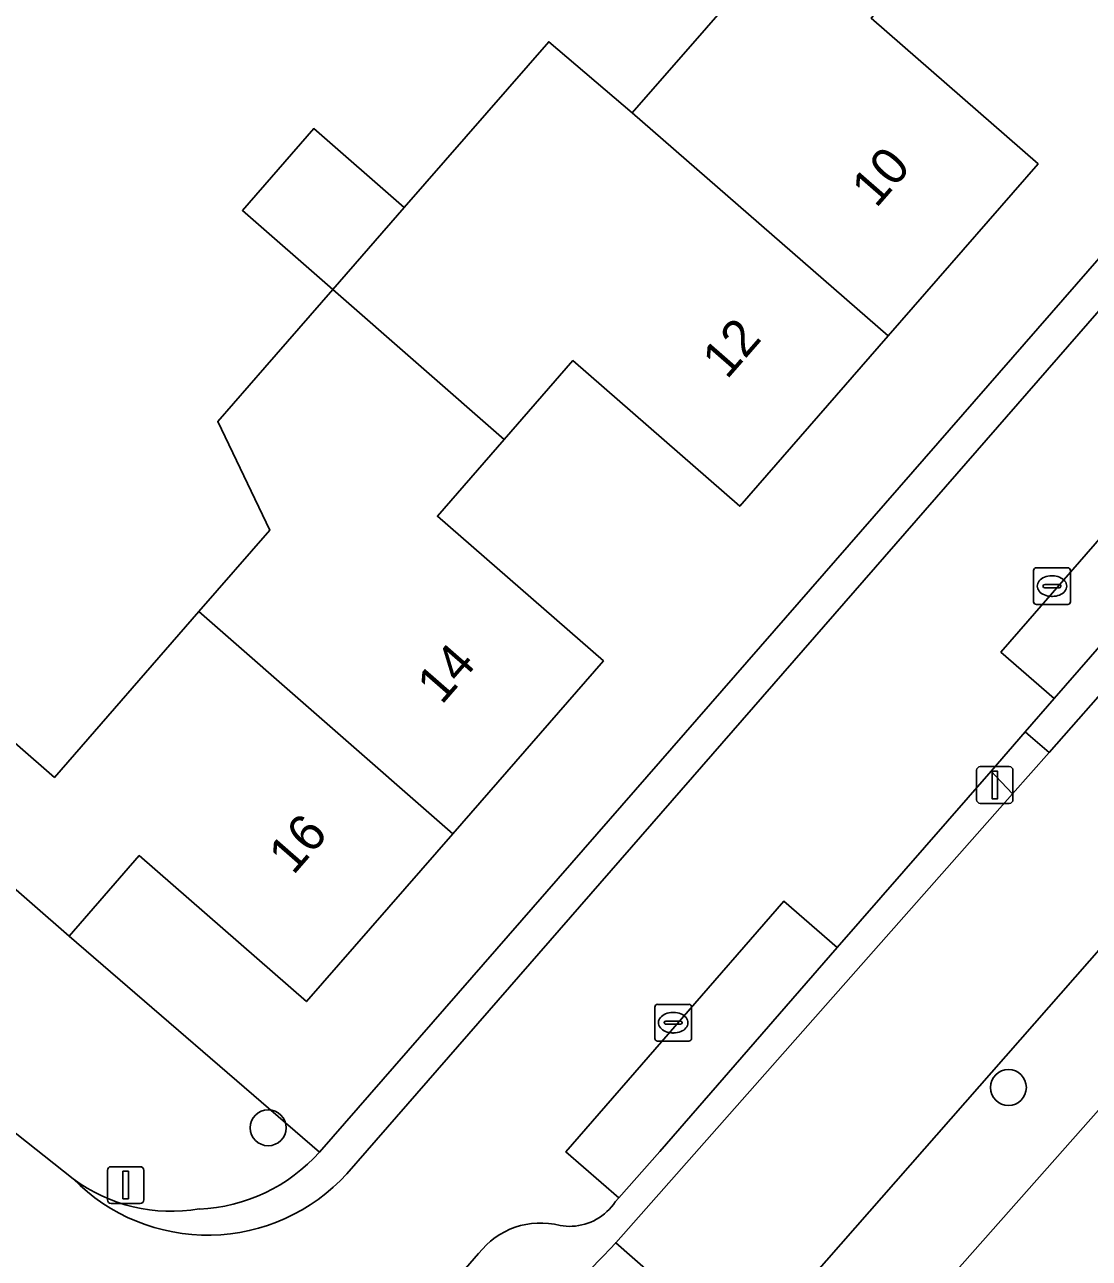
# Model space of a CAD drawing. Extents: x 158472 to 159562, y 388525 to 389606.
# Drawn here: x 158856.42 to 158885.42, y 388781.84 to 388815.42 of the extents above; entities that cross this region are included whole.
import ezdxf

# ---------------------------------------------------------------- set-up
doc = ezdxf.new("R2010")
doc.units = 0
for name, color, linetype in [('IMGEO_Berm_groen', 7, 'Continuous'), ('IMGEO_Boom', 7, 'Continuous'), ('IMGEO_Erf', 7, 'Continuous'), ('IMGEO_Fietspad_gesloten', 7, 'Continuous'), ('IMGEO_Groenvoorziening', 7, 'Continuous'), ('IMGEO_Haag', 7, 'Continuous'), ('IMGEO_Kolk', 7, 'Continuous'), ('IMGEO_Lichtmast', 7, 'Continuous'), ('IMGEO_Pand', 7, 'Continuous'), ('IMGEO_Pand_nummerreeks', 7, 'Continuous'), ('IMGEO_Parkeervlak_open', 7, 'Continuous'), ('IMGEO_Rijbaan_lokaal_open', 7, 'Continuous'), ('IMGEO_Voetpad_open', 7, 'Continuous')]:
    doc.layers.add(name, color=color, linetype=linetype)

msp = doc.modelspace()

# ---------------------------------------------------------------- linework, layer by layer
at = {"layer": 'IMGEO_Berm_groen'}
msp.add_lwpolyline([(158892.117, 388793.148), (158889.917, 388795.054), (158877.157, 388780.522), (158879.294, 388778.679)], close=True, dxfattribs=at)
at = {"layer": 'IMGEO_Boom'}
for centre in [(158883.214, 388786.491), (158863.054, 388785.394)]:
    msp.add_circle(centre, 0.489, dxfattribs=at)
at = {"layer": 'IMGEO_Erf'}
for points in [[(158879.477, 388815.598), (158884.025, 388811.633), (158879.94, 388806.948), (158875.899, 388802.313), (158871.353, 388806.277), (158869.482, 388804.131), (158867.662, 388802.043), (158872.182, 388798.102), (158868.082, 388793.4), (158864.097, 388788.83), (158859.542, 388792.802), (158857.634, 388790.614), (158864.451, 388784.733), (158911.812, 388839.017)], [(158852.973, 388798.644), (158857.231, 388794.932), (158861.165, 388799.444), (158863.096, 388801.659), (158861.678, 388804.616), (158862.96, 388806.086), (158864.814, 388808.212), (158862.352, 388810.365), (158864.295, 388812.593), (158866.76, 388810.444), (158870.695, 388814.957), (158872.971, 388813.02), (158877.015, 388817.658)]]:
    msp.add_lwpolyline(points, dxfattribs=at)
at = {"layer": 'IMGEO_Fietspad_gesloten'}
msp.add_lwpolyline([(158939.547, 388858.13), (158926.586, 388843.327), (158908.631, 388822.912), (158891.98, 388803.837), (158886.534, 388797.524), (158886.262, 388797.803), (158884.323, 388795.61), (158883.327, 388794.483), (158872.522, 388782.263), (158876.002, 388779.209), (158877.157, 388780.522), (158889.917, 388795.054), (158889.244, 388795.75), (158891.577, 388798.482), (158892.838, 388800.078), (158918.64, 388829.712), (158922.701, 388834.313), (158925.978, 388838.056), (158929.322, 388841.85), (158932.045, 388844.827), (158941.937, 388856.138)], dxfattribs=at)
at = {"layer": 'IMGEO_Groenvoorziening'}
for points in [[(158908.631, 388822.912), (158926.586, 388843.327), (158939.547, 388858.13), (158938.627, 388858.934), (158938.477, 388859.066), (158930.791, 388850.245), (158928.977, 388848.164), (158913.904, 388830.865), (158908.033, 388824.128), (158902.113, 388817.333), (158896.228, 388810.579), (158890.332, 388803.813), (158884.464, 388797.078), (158883.671, 388796.168), (158883.813, 388796.047), (158884.323, 388795.61), (158886.262, 388797.803), (158886.534, 388797.524), (158891.98, 388803.837)], [(158905.722, 388781.283), (158892.117, 388793.148), (158879.294, 388778.679), (158890.988, 388768.428), (158894.607, 388772.504), (158896.992, 388770.463), (158901.625, 388775.786), (158900.81, 388776.411), (158902.979, 388778.898), (158903.356, 388778.57)]]:
    msp.add_lwpolyline(points, close=True, dxfattribs=at)
for points in [[(158857.634, 388790.614), (158851.009, 388796.391), (158849.312, 388794.562), (158852.713, 388791.594)], [(158883.327, 388794.483), (158882.873, 388794.969), (158882.745, 388795.105), (158878.555, 388790.297), (158873.72, 388784.748), (158872.6, 388783.485), (158872.508, 388783.381)], [(158868.786, 388781.968), (158856.961, 388768.353), (158856.858, 388768.202), (158856.185, 388767.106), (158856.64, 388766.667), (158865.091, 388774.661), (158872.19, 388781.908), (158872.356, 388782.085), (158872.522, 388782.263), (158883.327, 388794.483)], [(158864.451, 388784.733), (158857.634, 388790.614)], [(158852.878, 388789.756), (158852.057, 388788.84), (158855.942, 388785.43), (158857.744, 388784.003)]]:
    msp.add_lwpolyline(points, dxfattribs=at)
for centre, radius, start, end in [((158860.989, 388787.814), 4.635, 272.3427, 318.3391), ((158860.419, 388787.605), 4.486, 233.3995, 279.7404), ((158871.267, 388784.196), 1.484, 272.4527, 326.701), ((158870.472, 388780.679), 2.123, 75.5218, 142.5995), ((158871.257, 388784.131), 1.42, 259.6887, 272.9846)]:
    msp.add_arc(centre, radius, start, end, dxfattribs=at)
at = {"layer": 'IMGEO_Haag'}
msp.add_lwpolyline([(158926.586, 388843.327), (158939.547, 388858.13), (158938.627, 388858.934), (158938.477, 388859.066), (158930.791, 388850.245), (158928.977, 388848.164), (158913.904, 388830.865), (158908.033, 388824.128), (158902.113, 388817.333), (158896.228, 388810.579), (158890.332, 388803.813), (158884.464, 388797.078), (158883.671, 388796.168), (158883.813, 388796.047), (158884.323, 388795.61), (158886.262, 388797.803), (158886.534, 388797.524), (158891.98, 388803.837), (158908.631, 388822.912)], close=True, dxfattribs=at)
for points in [[(158883.327, 388794.483), (158882.873, 388794.969), (158882.745, 388795.105), (158878.555, 388790.297), (158873.72, 388784.748), (158872.6, 388783.485), (158872.508, 388783.381)], [(158868.786, 388781.968), (158856.961, 388768.353), (158856.858, 388768.202), (158856.185, 388767.106), (158856.64, 388766.667), (158865.091, 388774.661), (158872.19, 388781.908), (158872.356, 388782.085), (158872.522, 388782.263), (158883.327, 388794.483)]]:
    msp.add_lwpolyline(points, dxfattribs=at)
for centre, radius, start, end in [((158871.267, 388784.196), 1.484, 272.4527, 326.701), ((158870.472, 388780.679), 2.123, 75.5218, 142.5995), ((158871.257, 388784.131), 1.42, 259.6887, 272.9846)]:
    msp.add_arc(centre, radius, start, end, dxfattribs=at)
at = {"layer": 'IMGEO_Kolk'}
for p, q in [((158883.902, 388799.713), (158883.902, 388800.565)), ((158883.977, 388800.639), (158884.829, 388800.639)), ((158884.903, 388800.565), (158884.903, 388799.713)), ((158884.161, 388800.133), (158884.161, 388800.145)), ((158884.204, 388800.182), (158884.602, 388800.182)), ((158884.39, 388800.419), (158884.415, 388800.419)), ((158884.645, 388800.145), (158884.645, 388800.133)), ((158884.599, 388800.096), (158884.201, 388800.096)), ((158884.413, 388799.859), (158884.388, 388799.859)), ((158884.829, 388799.639), (158883.977, 388799.639)), ((158873.659, 388788.754), (158874.511, 388788.754)), ((158873.584, 388787.828), (158873.584, 388788.68)), ((158874.072, 388788.534), (158874.097, 388788.534)), ((158874.585, 388788.68), (158874.585, 388787.828)), ((158873.843, 388788.248), (158873.843, 388788.26)), ((158874.281, 388788.211), (158873.883, 388788.211)), ((158873.886, 388788.297), (158874.284, 388788.297)), ((158874.327, 388788.26), (158874.327, 388788.248)), ((158874.511, 388787.754), (158873.659, 388787.754)), ((158874.095, 388787.974), (158874.07, 388787.974))]:
    msp.add_line(p, q, dxfattribs=at)
for points in [[(158883.902, 388799.713), (158883.902, 388800.565)], [(158883.977, 388800.639), (158884.829, 388800.639)], [(158884.903, 388800.565), (158884.903, 388799.713)], [(158884.829, 388799.639), (158883.977, 388799.639)], [(158873.659, 388788.754), (158874.511, 388788.754)], [(158873.584, 388787.828), (158873.584, 388788.68)], [(158874.585, 388788.68), (158874.585, 388787.828)], [(158874.511, 388787.754), (158873.659, 388787.754)]]:
    msp.add_lwpolyline(points, dxfattribs=at)
for centre, radius, start, end in [((158883.979, 388800.563), 0.0765, 91.552, 178.448), ((158883.979, 388800.563), 0.0765, 91.552, 178.448), ((158884.827, 388800.563), 0.0765, 1.552, 88.448), ((158884.827, 388800.563), 0.0765, 1.552, 88.448), ((158884.201, 388800.142), 0.0403, 85.8775, 175.7526), ((158884.606, 388800.144), 0.0386, 1.7309, 96.639), ((158884.198, 388800.132), 0.0366, 178.938, 274.7102), ((158884.602, 388800.139), 0.043, 264.8664, 352.4533), ((158883.979, 388799.715), 0.0765, 181.552, 268.448), ((158883.979, 388799.715), 0.0765, 181.552, 268.448), ((158884.827, 388799.715), 0.0765, 271.552, 358.448), ((158884.827, 388799.715), 0.0765, 271.552, 358.448), ((158873.661, 388788.678), 0.0765, 91.552, 178.448), ((158873.661, 388788.678), 0.0765, 91.552, 178.448), ((158874.509, 388788.678), 0.0765, 1.552, 88.448), ((158874.509, 388788.678), 0.0765, 1.552, 88.448), ((158873.883, 388788.257), 0.0403, 85.8775, 175.7526), ((158873.88, 388788.247), 0.0366, 178.938, 274.7102), ((158874.284, 388788.254), 0.043, 264.8664, 352.4533), ((158874.288, 388788.259), 0.0386, 1.7309, 96.639), ((158873.661, 388787.83), 0.0765, 181.552, 268.448), ((158873.661, 388787.83), 0.0765, 181.552, 268.448), ((158874.509, 388787.83), 0.0765, 271.552, 358.448), ((158874.509, 388787.83), 0.0765, 271.552, 358.448)]:
    msp.add_arc(centre, radius, start, end, dxfattribs=at)
for centre, major_axis, ratio, start_param, end_param in [((158884.389, 388800.139), (-0.387, 0.002), 0.722429, 4.712389, 7.853982), ((158884.414, 388800.139), (-0.39, 0.002), 0.717154, 1.570796, 4.712389), ((158874.071, 388788.254), (-0.387, 0.002), 0.722429, 4.712389, 7.853982), ((158874.096, 388788.254), (-0.39, 0.002), 0.717154, 1.570796, 4.712389)]:
    msp.add_ellipse(centre, major_axis=major_axis, ratio=ratio, start_param=start_param, end_param=end_param, dxfattribs=at)
at = {"layer": 'IMGEO_Lichtmast'}
for p, q in [((158882.349, 388794.325), (158882.349, 388795.125)), ((158882.349, 388795.125), (158882.349, 388794.325)), ((158882.449, 388795.225), (158883.239, 388795.225)), ((158883.239, 388795.225), (158882.449, 388795.225)), ((158883.339, 388795.125), (158883.339, 388794.325)), ((158883.339, 388794.325), (158883.339, 388795.125)), ((158883.239, 388794.225), (158882.449, 388794.225)), ((158882.449, 388794.225), (158883.239, 388794.225)), ((158858.675, 388783.435), (158858.675, 388784.235)), ((158858.675, 388784.235), (158858.675, 388783.435)), ((158858.775, 388784.335), (158859.565, 388784.335)), ((158859.565, 388784.335), (158858.775, 388784.335)), ((158859.665, 388784.235), (158859.665, 388783.435)), ((158859.665, 388783.435), (158859.665, 388784.235)), ((158859.565, 388783.335), (158858.775, 388783.335)), ((158858.775, 388783.335), (158859.565, 388783.335))]:
    msp.add_line(p, q, dxfattribs=at)
for points in [[(158882.769, 388795.1), (158882.919, 388795.1), (158882.919, 388794.35), (158882.769, 388794.35), (158882.769, 388795.1)], [(158859.095, 388784.21), (158859.245, 388784.21), (158859.245, 388783.46), (158859.095, 388783.46), (158859.095, 388784.21)]]:
    msp.add_lwpolyline(points, dxfattribs=at)
for centre, start, end in [((158882.449, 388795.125), 90, 180), ((158882.449, 388795.125), 90, 180), ((158883.239, 388795.125), 0, 90), ((158883.239, 388795.125), 360, 90), ((158882.449, 388794.325), 180, 270), ((158882.449, 388794.325), 180, 270), ((158883.239, 388794.325), 270, 0), ((158883.239, 388794.325), 270, 0), ((158858.775, 388784.235), 90, 180), ((158858.775, 388784.235), 90, 180), ((158859.565, 388784.235), 0, 90), ((158859.565, 388784.235), 360, 90), ((158858.775, 388783.435), 180, 270), ((158858.775, 388783.435), 180, 270), ((158859.565, 388783.435), 270, 0), ((158859.565, 388783.435), 270, 0)]:
    msp.add_arc(centre, 0.1, start, end, dxfattribs=at)
at = {"layer": 'IMGEO_Pand'}
for points in [[(158872.971, 388813.02), (158879.94, 388806.948), (158884.025, 388811.633), (158879.477, 388815.598), (158881.307, 388817.697), (158876.672, 388821.745), (158874.796, 388819.593), (158877.015, 388817.658)], [(158872.971, 388813.02), (158870.695, 388814.957), (158866.76, 388810.444), (158864.814, 388808.212), (158869.482, 388804.131), (158871.353, 388806.277), (158875.899, 388802.313), (158879.94, 388806.948)], [(158866.76, 388810.444), (158864.295, 388812.593), (158862.352, 388810.365), (158864.814, 388808.212)], [(158869.482, 388804.131), (158864.814, 388808.212), (158862.96, 388806.086), (158861.678, 388804.616), (158863.096, 388801.659), (158861.165, 388799.444), (158868.082, 388793.4), (158872.182, 388798.102), (158867.662, 388802.043)], [(158868.082, 388793.4), (158861.165, 388799.444), (158857.231, 388794.932), (158852.973, 388798.644), (158851.009, 388796.391), (158857.634, 388790.614), (158859.542, 388792.802), (158864.097, 388788.83)]]:
    msp.add_lwpolyline(points, close=True, dxfattribs=at)
at = {"layer": 'IMGEO_Parkeervlak_open'}
for points in [[(158890.332, 388803.813), (158888.88, 388805.079), (158883.011, 388798.345), (158884.464, 388797.078)], [(158872.6, 388783.485), (158873.72, 388784.748), (158878.555, 388790.297), (158877.101, 388791.564), (158871.161, 388784.739)]]:
    msp.add_lwpolyline(points, close=True, dxfattribs=at)
at = {"layer": 'IMGEO_Rijbaan_lokaal_open'}
for points in [[(158896.228, 388810.579), (158894.776, 388811.844), (158900.662, 388818.597), (158902.113, 388817.333), (158908.033, 388824.128), (158906.584, 388825.391), (158912.453, 388832.13), (158913.904, 388830.865), (158928.977, 388848.164), (158925.739, 388851.017), (158923.631, 388848.586), (158922.361, 388847.122), (158916.285, 388840.115), (158914.973, 388841.243), (158865.195, 388784.143)], [(158872.508, 388783.381), (158872.6, 388783.485), (158871.161, 388784.739), (158877.101, 388791.564), (158878.555, 388790.297), (158882.745, 388795.105), (158883.671, 388796.168), (158884.464, 388797.078), (158883.011, 388798.345), (158888.88, 388805.079), (158890.332, 388803.813), (158896.228, 388810.579)], [(158857.744, 388784.003), (158855.942, 388785.43), (158855.535, 388784.987), (158855.447, 388784.891), (158853.619, 388782.898)], [(158852.007, 388753.63), (158856.673, 388759.016), (158860.029, 388762.746), (158860.801, 388762.084), (158865.568, 388767.347), (158873.175, 388775.995), (158876.002, 388779.209), (158872.522, 388782.263), (158872.356, 388782.085), (158872.19, 388781.908), (158865.091, 388774.661), (158856.64, 388766.667), (158855.357, 388765.589)], [(158854.314, 388770.621), (158854.216, 388770.482), (158855.756, 388769.138), (158856.858, 388768.202), (158856.961, 388768.353), (158868.786, 388781.968)]]:
    msp.add_lwpolyline(points, dxfattribs=at)
for centre, radius, start, end in [((158861.403, 388787.601), 5.132, 224.514, 317.6389), ((158871.267, 388784.196), 1.484, 272.4527, 326.701), ((158870.472, 388780.679), 2.123, 75.5218, 142.5995), ((158871.257, 388784.131), 1.42, 259.6887, 272.9846)]:
    msp.add_arc(centre, radius, start, end, dxfattribs=at)
at = {"layer": 'IMGEO_Voetpad_open'}
for points in [[(158932.289, 388858.569), (158930.295, 388860.304), (158929.092, 388858.899), (158923.245, 388852.106), (158919.136, 388847.412), (158911.812, 388839.017), (158864.451, 388784.733)], [(158865.195, 388784.143), (158914.973, 388841.243), (158921.074, 388848.243), (158922.361, 388847.122), (158923.631, 388848.586), (158922.347, 388849.704), (158928.27, 388856.495), (158929.535, 388855.393), (158932.289, 388858.569)]]:
    msp.add_lwpolyline(points, dxfattribs=at)
msp.add_lwpolyline([(158884.323, 388795.61), (158883.813, 388796.047), (158883.671, 388796.168), (158882.745, 388795.105), (158882.873, 388794.969), (158883.327, 388794.483)], close=True, dxfattribs=at)
for centre, radius, start, end in [((158860.989, 388787.814), 4.635, 272.3427, 318.3391), ((158861.403, 388787.601), 5.132, 224.514, 317.6389), ((158860.419, 388787.605), 4.486, 233.3995, 279.7404)]:
    msp.add_arc(centre, radius, start, end, dxfattribs=at)

# ---------------------------------------------------------------- texts
at = {"layer": 'IMGEO_Pand_nummerreeks'}
for s, rotation, p in [('10', 48.9152, (158879.613, 388810.407)), ('12', 48.9134, (158875.546, 388805.743)), ('14', 48.9134, (158867.778, 388796.886)), ('16', 48.9122, (158863.736, 388792.25))]:
    msp.add_text(s, height=1, rotation=rotation, dxfattribs=at).set_placement(p)

doc.saveas('drawing.dxf')
